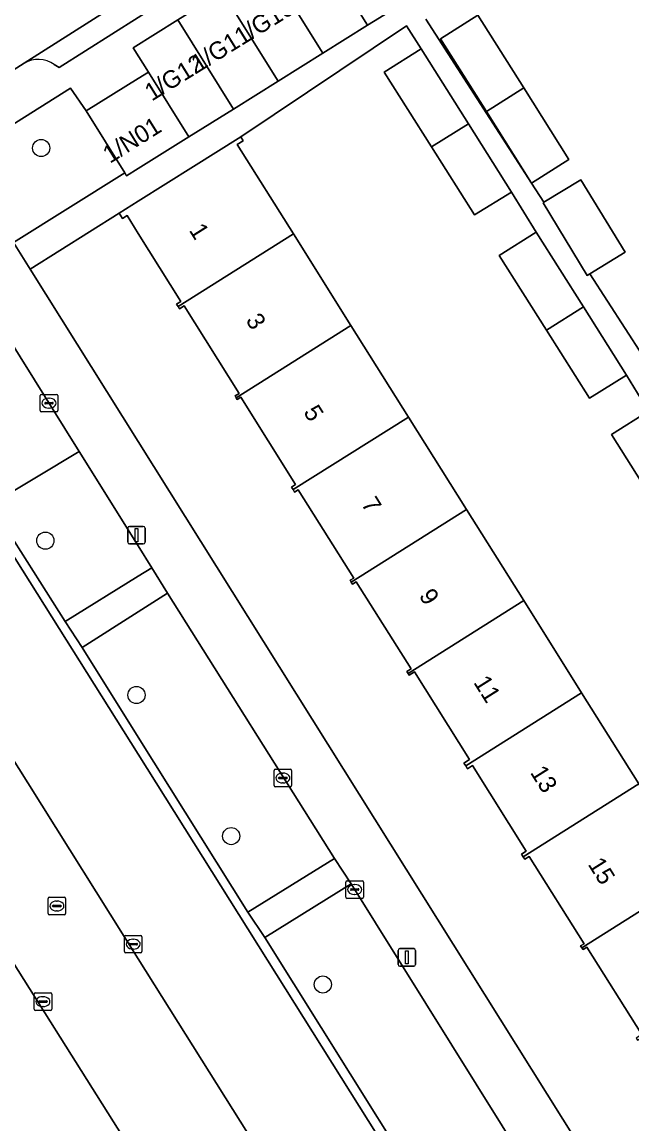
# Model space of a CAD drawing. Extents: x 160077 to 160948, y 386481 to 387498.
# Drawn here: x 160493.4 to 160528.1, y 386782.4 to 386845.2 of the extents above; entities that cross this region are included whole.
import ezdxf

# ---------------------------------------------------------------- set-up
doc = ezdxf.new("R2010")
doc.units = 0
for name, color, linetype in [('IMGEO_Boom', 7, 'Continuous'), ('IMGEO_Erf', 7, 'Continuous'), ('IMGEO_Groenvoorziening', 7, 'Continuous'), ('IMGEO_Kolk', 7, 'Continuous'), ('IMGEO_Lichtmast', 7, 'Continuous'), ('IMGEO_Pand', 7, 'Continuous'), ('IMGEO_Pand_nummerreeks', 7, 'Continuous'), ('IMGEO_Parkeervlak_open', 7, 'Continuous'), ('IMGEO_Rijbaan_lokaal_open', 7, 'Continuous'), ('IMGEO_Rioolput', 7, 'Continuous'), ('IMGEO_Voetpad_open', 7, 'Continuous')]:
    doc.layers.add(name, color=color, linetype=linetype)

msp = doc.modelspace()

# ---------------------------------------------------------------- linework, layer by layer
at = {"layer": 'IMGEO_Boom'}
for centre in [(160494.468, 386837.987), (160494.706, 386815.629), (160499.897, 386806.838), (160505.295, 386798.805), (160510.52, 386790.355)]:
    msp.add_circle(centre, 0.489, dxfattribs=at)
at = {"layer": 'IMGEO_Erf'}
msp.add_lwpolyline([(160522.416, 386835.99), (160519.84, 386840.073), (160517.231, 386844.212), (160519.359, 386845.554), (160521.969, 386841.416), (160524.544, 386837.332)], close=True, dxfattribs=at)
for points in [[(160529.827, 386817.16), (160526.976, 386821.668), (160529.07, 386822.996), (160527.823, 386825.053), (160525.713, 386823.751), (160523.266, 386827.62), (160520.575, 386831.875), (160522.669, 386833.203), (160521.27, 386835.483), (160519.16, 386834.181), (160516.713, 386838.05), (160514.022, 386842.305), (160516.116, 386843.633), (160515.286, 386844.946), (160505.836, 386838.631), (160505.98, 386838.401), (160505.645, 386838.19), (160508.843, 386833.1), (160512.119, 386827.886), (160515.396, 386822.67), (160518.708, 386817.399), (160521.966, 386812.214), (160525.268, 386806.959), (160528.526, 386801.773)], [(160516.381, 386845.329), (160522.416, 386835.99), (160523.119, 386834.899), (160525.219, 386836.185), (160527.742, 386832.055), (160525.741, 386830.829), (160530.763, 386823.035), (160546.111, 386822.428), (160546.21, 386824.94), (160553.278, 386824.66), (160553.179, 386822.148), (160554.431, 386822.098), (160554.53, 386824.611), (160559.386, 386824.418), (160564.241, 386824.226), (160564.142, 386821.714), (160566.735, 386821.612), (160566.834, 386824.124), (160571.69, 386823.932)], [(160528.702, 386787.499), (160525.566, 386792.477), (160525.351, 386792.338), (160525.279, 386792.445), (160525.207, 386792.552), (160525.406, 386792.677), (160522.284, 386797.646), (160522.03, 386797.487), (160521.94, 386797.63), (160521.849, 386797.775), (160522.115, 386797.942), (160519.049, 386802.821), (160518.762, 386802.64), (160518.66, 386802.802), (160518.558, 386802.965), (160518.876, 386803.165), (160515.741, 386808.154), (160515.439, 386807.964), (160515.374, 386808.067), (160515.308, 386808.172), (160515.545, 386808.321), (160512.422, 386813.292), (160512.211, 386813.16), (160512.142, 386813.268), (160512.075, 386813.375), (160512.279, 386813.502), (160509.122, 386818.527), (160508.907, 386818.392), (160508.819, 386818.533), (160508.73, 386818.675), (160508.967, 386818.824), (160505.84, 386823.802), (160505.632, 386823.671), (160505.576, 386823.77), (160505.519, 386823.871), (160505.748, 386824.014), (160502.614, 386829.002), (160502.347, 386828.834), (160502.266, 386828.963), (160502.185, 386829.092), (160502.435, 386829.249), (160500, 386833.124), (160499.363, 386834.138), (160499.106, 386833.977), (160498.914, 386834.282), (160493.843, 386831.09), (160500, 386821.271), (160533.22, 386768.294)]]:
    msp.add_lwpolyline(points, dxfattribs=at)
at = {"layer": 'IMGEO_Groenvoorziening'}
for points in [[(160491.599, 386834.684), (160492.889, 386832.611), (160499.231, 386836.575), (160497.03, 386840.097), (160496.129, 386841.406), (160492.636, 386839.201)], [(160484.287, 386836.124), (160481.322, 386834.24), (160491.654, 386817.735), (160496.638, 386820.704), (160487.431, 386835.412)], [(160492.95, 386815.59), (160495.843, 386811.033), (160500, 386813.607), (160500.779, 386814.089), (160500, 386815.333), (160496.638, 386820.704), (160491.654, 386817.735), (160490.344, 386816.955)]]:
    msp.add_lwpolyline(points, dxfattribs=at)
for points in [[(160506.249, 386794.478), (160511.177, 386797.531), (160501.675, 386812.637), (160500, 386811.578), (160496.797, 386809.553), (160500, 386804.445)], [(160520.143, 386772.386), (160525.003, 386775.498), (160512.129, 386796.086), (160507.211, 386793.022)]]:
    msp.add_lwpolyline(points, close=True, dxfattribs=at)
at = {"layer": 'IMGEO_Kolk'}
for p, q in [((160494.413, 386823.035), (160494.413, 386823.887)), ((160494.488, 386823.961), (160495.34, 386823.961)), ((160494.672, 386823.455), (160494.672, 386823.467)), ((160495.11, 386823.418), (160494.712, 386823.418)), ((160494.715, 386823.504), (160495.113, 386823.504)), ((160494.901, 386823.741), (160494.926, 386823.741)), ((160495.156, 386823.467), (160495.156, 386823.455)), ((160495.414, 386823.887), (160495.414, 386823.035)), ((160495.34, 386822.961), (160494.488, 386822.961)), ((160494.924, 386823.181), (160494.899, 386823.181)), ((160511.833, 386795.334), (160511.833, 386796.186)), ((160511.908, 386796.26), (160512.76, 386796.26)), ((160512.135, 386795.803), (160512.533, 386795.803)), ((160512.321, 386796.04), (160512.346, 386796.04)), ((160512.834, 386796.186), (160512.834, 386795.334)), ((160512.76, 386795.26), (160511.908, 386795.26)), ((160512.092, 386795.754), (160512.092, 386795.766)), ((160512.53, 386795.717), (160512.132, 386795.717)), ((160512.344, 386795.48), (160512.319, 386795.48)), ((160512.576, 386795.766), (160512.576, 386795.754)), ((160499.21, 386792.224), (160499.21, 386793.076)), ((160499.285, 386793.15), (160500.137, 386793.15)), ((160499.512, 386792.693), (160499.91, 386792.693)), ((160499.698, 386792.93), (160499.723, 386792.93)), ((160500.211, 386793.076), (160500.211, 386792.224)), ((160500.137, 386792.15), (160499.285, 386792.15)), ((160499.469, 386792.644), (160499.469, 386792.656)), ((160499.907, 386792.607), (160499.509, 386792.607)), ((160499.721, 386792.37), (160499.696, 386792.37)), ((160499.953, 386792.656), (160499.953, 386792.644)), ((160494.067, 386788.954), (160494.067, 386789.806)), ((160494.142, 386789.88), (160494.994, 386789.88)), ((160494.555, 386789.66), (160494.58, 386789.66)), ((160495.068, 386789.806), (160495.068, 386788.954)), ((160494.326, 386789.374), (160494.326, 386789.386)), ((160494.764, 386789.337), (160494.366, 386789.337)), ((160494.369, 386789.423), (160494.767, 386789.423)), ((160494.578, 386789.1), (160494.553, 386789.1)), ((160494.81, 386789.386), (160494.81, 386789.374)), ((160494.994, 386788.88), (160494.142, 386788.88))]:
    msp.add_line(p, q, dxfattribs=at)
for points in [[(160494.413, 386823.035), (160494.413, 386823.887)], [(160494.488, 386823.961), (160495.34, 386823.961)], [(160495.414, 386823.887), (160495.414, 386823.035)], [(160495.34, 386822.961), (160494.488, 386822.961)], [(160511.833, 386795.334), (160511.833, 386796.186)], [(160511.908, 386796.26), (160512.76, 386796.26)], [(160512.834, 386796.186), (160512.834, 386795.334)], [(160512.76, 386795.26), (160511.908, 386795.26)], [(160499.21, 386792.224), (160499.21, 386793.076)], [(160499.285, 386793.15), (160500.137, 386793.15)], [(160500.211, 386793.076), (160500.211, 386792.224)], [(160500.137, 386792.15), (160499.285, 386792.15)], [(160494.067, 386788.954), (160494.067, 386789.806)], [(160494.142, 386789.88), (160494.994, 386789.88)], [(160495.068, 386789.806), (160495.068, 386788.954)], [(160494.994, 386788.88), (160494.142, 386788.88)]]:
    msp.add_lwpolyline(points, dxfattribs=at)
for centre, radius, start, end in [((160494.49, 386823.885), 0.0765, 91.55205, 178.44795), ((160494.49, 386823.885), 0.0765, 91.55205, 178.44795), ((160494.712, 386823.464), 0.0403, 85.87752, 175.75265), ((160494.709, 386823.454), 0.0366, 178.93798, 274.71019), ((160495.113, 386823.461), 0.043, 264.86636, 352.45326), ((160495.117, 386823.466), 0.0386, 1.73085, 96.63898), ((160495.338, 386823.885), 0.0765, 1.55205, 88.44795), ((160495.338, 386823.885), 0.0765, 1.55205, 88.44795), ((160494.49, 386823.037), 0.0765, 181.55205, 268.44795), ((160494.49, 386823.037), 0.0765, 181.55205, 268.44795), ((160495.338, 386823.037), 0.0765, 271.55205, 358.44795), ((160495.338, 386823.037), 0.0765, 271.55205, 358.44795), ((160511.91, 386796.184), 0.0765, 91.55205, 178.44795), ((160511.91, 386796.184), 0.0765, 91.55205, 178.44795), ((160512.132, 386795.763), 0.0403, 85.87752, 175.75265), ((160512.537, 386795.765), 0.0386, 1.73085, 96.63898), ((160512.758, 386796.184), 0.0765, 1.55205, 88.44795), ((160512.758, 386796.184), 0.0765, 1.55205, 88.44795), ((160511.91, 386795.336), 0.0765, 181.55205, 268.44795), ((160511.91, 386795.336), 0.0765, 181.55205, 268.44795), ((160512.129, 386795.753), 0.0366, 178.93798, 274.71019), ((160512.533, 386795.76), 0.043, 264.86636, 352.45326), ((160512.758, 386795.336), 0.0765, 271.55205, 358.44795), ((160512.758, 386795.336), 0.0765, 271.55205, 358.44795), ((160499.287, 386793.074), 0.0765, 91.55205, 178.44795), ((160499.287, 386793.074), 0.0765, 91.55205, 178.44795), ((160499.509, 386792.653), 0.0403, 85.87752, 175.75265), ((160499.914, 386792.655), 0.0386, 1.73085, 96.63898), ((160500.135, 386793.074), 0.0765, 1.55205, 88.44795), ((160500.135, 386793.074), 0.0765, 1.55205, 88.44795), ((160499.287, 386792.226), 0.0765, 181.55205, 268.44795), ((160499.287, 386792.226), 0.0765, 181.55205, 268.44795), ((160499.506, 386792.643), 0.0366, 178.93798, 274.71019), ((160499.91, 386792.65), 0.043, 264.86636, 352.45326), ((160500.135, 386792.226), 0.0765, 271.55205, 358.44795), ((160500.135, 386792.226), 0.0765, 271.55205, 358.44795), ((160494.144, 386789.804), 0.0765, 91.55205, 178.44795), ((160494.144, 386789.804), 0.0765, 91.55205, 178.44795), ((160494.992, 386789.804), 0.0765, 1.55205, 88.44795), ((160494.992, 386789.804), 0.0765, 1.55205, 88.44795), ((160494.144, 386788.956), 0.0765, 181.55205, 268.44795), ((160494.144, 386788.956), 0.0765, 181.55205, 268.44795), ((160494.366, 386789.383), 0.0403, 85.87752, 175.75265), ((160494.363, 386789.373), 0.0366, 178.93798, 274.71019), ((160494.767, 386789.38), 0.043, 264.86636, 352.45326), ((160494.771, 386789.385), 0.0386, 1.73085, 96.63898), ((160494.992, 386788.956), 0.0765, 271.55205, 358.44795), ((160494.992, 386788.956), 0.0765, 271.55205, 358.44795)]:
    msp.add_arc(centre, radius, start, end, dxfattribs=at)
for centre, major_axis, ratio, start_param, end_param in [((160494.9, 386823.461), (-0.387, 0.002), 0.722429, 4.712389, 7.853982), ((160494.925, 386823.461), (-0.39, 0.002), 0.717154, 1.570796, 4.712389), ((160512.32, 386795.76), (-0.387, 0.002), 0.722429, 4.712389, 7.853982), ((160512.345, 386795.76), (-0.39, 0.002), 0.717154, 1.570796, 4.712389), ((160499.697, 386792.65), (-0.387, 0.002), 0.722429, 4.712389, 7.853982), ((160499.722, 386792.65), (-0.39, 0.002), 0.717154, 1.570796, 4.712389), ((160494.554, 386789.38), (-0.387, 0.002), 0.722429, 4.712389, 7.853982), ((160494.579, 386789.38), (-0.39, 0.002), 0.717154, 1.570796, 4.712389)]:
    msp.add_ellipse(centre, major_axis=major_axis, ratio=ratio, start_param=start_param, end_param=end_param, dxfattribs=at)
at = {"layer": 'IMGEO_Lichtmast'}
for p, q in [((160499.398, 386815.542), (160499.398, 386816.342)), ((160499.398, 386816.342), (160499.398, 386815.542)), ((160499.498, 386816.442), (160500.288, 386816.442)), ((160500.288, 386816.442), (160499.498, 386816.442)), ((160500.388, 386816.342), (160500.388, 386815.542)), ((160500.388, 386815.542), (160500.388, 386816.342)), ((160500.288, 386815.442), (160499.498, 386815.442)), ((160499.498, 386815.442), (160500.288, 386815.442)), ((160514.806, 386791.496), (160514.806, 386792.296)), ((160514.806, 386792.296), (160514.806, 386791.496)), ((160514.906, 386792.396), (160515.696, 386792.396)), ((160515.696, 386792.396), (160514.906, 386792.396)), ((160515.796, 386792.296), (160515.796, 386791.496)), ((160515.796, 386791.496), (160515.796, 386792.296)), ((160515.696, 386791.396), (160514.906, 386791.396)), ((160514.906, 386791.396), (160515.696, 386791.396))]:
    msp.add_line(p, q, dxfattribs=at)
for points in [[(160499.818, 386816.317), (160499.968, 386816.317), (160499.968, 386815.567), (160499.818, 386815.567), (160499.818, 386816.317)], [(160515.226, 386792.271), (160515.376, 386792.271), (160515.376, 386791.521), (160515.226, 386791.521), (160515.226, 386792.271)]]:
    msp.add_lwpolyline(points, dxfattribs=at)
for centre, start, end in [((160499.498, 386816.342), 90, 180), ((160499.498, 386816.342), 90, 180), ((160500.288, 386816.342), 0, 90), ((160500.288, 386816.342), 360, 90), ((160499.498, 386815.542), 180, 270), ((160499.498, 386815.542), 180, 270), ((160500.288, 386815.542), 270, 0), ((160500.288, 386815.542), 270, 0), ((160514.906, 386792.296), 90, 180), ((160514.906, 386792.296), 90, 180), ((160515.696, 386792.296), 0, 90), ((160515.696, 386792.296), 360, 90), ((160514.906, 386791.496), 180, 270), ((160514.906, 386791.496), 180, 270), ((160515.696, 386791.496), 270, 0), ((160515.696, 386791.496), 270, 0)]:
    msp.add_arc(centre, 0.1, start, end, dxfattribs=at)
at = {"layer": 'IMGEO_Pand'}
for points in [[(160512.43, 386851.65), (160509.886, 386850.06), (160513.061, 386844.979), (160515.606, 386846.569)], [(160510.516, 386843.389), (160513.061, 386844.979), (160509.886, 386850.06), (160507.341, 386848.47)], [(160507.341, 386848.47), (160504.796, 386846.88), (160507.972, 386841.799), (160510.516, 386843.389)], [(160505.427, 386840.208), (160507.972, 386841.799), (160504.796, 386846.88), (160502.252, 386845.29)], [(160519.84, 386840.073), (160521.969, 386841.416), (160519.359, 386845.554), (160517.231, 386844.212)], [(160502.882, 386838.618), (160505.427, 386840.208), (160502.252, 386845.29), (160499.707, 386843.7), (160500.574, 386842.312)], [(160516.116, 386843.633), (160514.022, 386842.305), (160516.713, 386838.05), (160518.812, 386839.37)], [(160500.574, 386842.312), (160500, 386841.953), (160497.03, 386840.097), (160499.231, 386836.575), (160499.338, 386836.404), (160500, 386836.818), (160502.882, 386838.618)], [(160521.969, 386841.416), (160519.84, 386840.073), (160522.416, 386835.99), (160524.544, 386837.332)], [(160519.16, 386834.181), (160521.27, 386835.483), (160518.812, 386839.37), (160516.713, 386838.05)], [(160508.843, 386833.1), (160505.645, 386838.19), (160505.98, 386838.401), (160505.836, 386838.631), (160503.148, 386836.942), (160500, 386834.964), (160498.914, 386834.282), (160499.106, 386833.977), (160499.363, 386834.138), (160500, 386833.124), (160502.435, 386829.249), (160502.185, 386829.092), (160502.266, 386828.963)], [(160523.119, 386834.899), (160523.067, 386834.867), (160525.59, 386830.737), (160525.741, 386830.829), (160527.742, 386832.055), (160525.219, 386836.185)], [(160502.266, 386828.963), (160502.347, 386828.834), (160502.614, 386829.002), (160505.748, 386824.014), (160505.519, 386823.871), (160505.576, 386823.77), (160512.119, 386827.886), (160508.843, 386833.1)], [(160522.669, 386833.203), (160520.575, 386831.875), (160523.266, 386827.62), (160525.365, 386828.94)], [(160525.713, 386823.751), (160527.823, 386825.053), (160525.365, 386828.94), (160523.266, 386827.62)], [(160515.396, 386822.67), (160512.119, 386827.886), (160505.576, 386823.77), (160505.632, 386823.671), (160505.84, 386823.802), (160508.967, 386818.824), (160508.73, 386818.675), (160508.819, 386818.533)], [(160531.926, 386818.48), (160529.07, 386822.996), (160526.976, 386821.668), (160529.827, 386817.16)], [(160508.819, 386818.533), (160508.907, 386818.392), (160509.122, 386818.527), (160512.279, 386813.502), (160512.075, 386813.375), (160512.142, 386813.268), (160518.708, 386817.399), (160515.396, 386822.67)], [(160521.966, 386812.214), (160518.708, 386817.399), (160512.142, 386813.268), (160512.211, 386813.16), (160512.422, 386813.292), (160515.545, 386808.321), (160515.308, 386808.172), (160515.374, 386808.067)], [(160515.374, 386808.067), (160515.439, 386807.964), (160515.741, 386808.154), (160518.876, 386803.165), (160518.558, 386802.965), (160518.66, 386802.802), (160525.268, 386806.959), (160521.966, 386812.214)], [(160528.526, 386801.773), (160525.268, 386806.959), (160518.66, 386802.802), (160518.762, 386802.64), (160519.049, 386802.821), (160522.115, 386797.942), (160521.849, 386797.775), (160521.94, 386797.63)], [(160531.807, 386796.552), (160528.526, 386801.773), (160521.94, 386797.63), (160522.03, 386797.487), (160522.284, 386797.646), (160525.406, 386792.677), (160525.207, 386792.552), (160525.279, 386792.445)], [(160535.077, 386791.347), (160537.583, 386792.921), (160534.313, 386798.126), (160531.807, 386796.552), (160525.279, 386792.445), (160525.351, 386792.338), (160525.566, 386792.477), (160528.702, 386787.499), (160528.377, 386787.294), (160528.45, 386787.178)]]:
    msp.add_lwpolyline(points, close=True, dxfattribs=at)
at = {"layer": 'IMGEO_Parkeervlak_open'}
for points in [[(160506.313, 386770.262), (160484.216, 386805.302), (160473.247, 386822.633)], [(160525.691, 386762.559), (160500, 386803.462), (160492.571, 386815.272)], [(160485.3, 386815.198), (160493.709, 386801.834), (160500, 386791.819), (160509.431, 386776.805), (160521.564, 386757.591), (160525.066, 386759.804)]]:
    msp.add_lwpolyline(points, dxfattribs=at)
at = {"layer": 'IMGEO_Rijbaan_lokaal_open'}
for points in [[(160480.194, 386834.45), (160485.71, 386837.9), (160486.605, 386838.46), (160493.492, 386842.826), (160500, 386846.953), (160519.43, 386859.272), (160532.054, 386867.023), (160535.096, 386868.978), (160531.426, 386874.903), (160528.456, 386873.047), (160507.768, 386860.017), (160500, 386855.149), (160485.425, 386846.014), (160475.724, 386839.906)], [(160500, 386791.819), (160493.709, 386801.834), (160485.3, 386815.198), (160478.374, 386826.207)], [(160473.247, 386822.633), (160484.216, 386805.302), (160506.313, 386770.262), (160512.49, 386760.505), (160513.375, 386759.047), (160516.389, 386754.32), (160516.594, 386754.45), (160521.564, 386757.591), (160509.431, 386776.805), (160500, 386791.819)]]:
    msp.add_lwpolyline(points, dxfattribs=at)
at = {"layer": 'IMGEO_Rioolput'}
for p, q in [((160507.74, 386801.685), (160507.74, 386802.537)), ((160507.815, 386802.611), (160508.667, 386802.611)), ((160507.999, 386802.105), (160507.999, 386802.117)), ((160508.042, 386802.154), (160508.44, 386802.154)), ((160508.228, 386802.391), (160508.253, 386802.391)), ((160508.483, 386802.117), (160508.483, 386802.105)), ((160508.741, 386802.537), (160508.741, 386801.685)), ((160508.667, 386801.611), (160507.815, 386801.611)), ((160508.437, 386802.068), (160508.039, 386802.068)), ((160508.251, 386801.831), (160508.226, 386801.831)), ((160494.861, 386794.395), (160494.861, 386795.247)), ((160494.936, 386795.321), (160495.788, 386795.321)), ((160495.862, 386795.247), (160495.862, 386794.395)), ((160495.12, 386794.815), (160495.12, 386794.827)), ((160495.558, 386794.778), (160495.16, 386794.778)), ((160495.163, 386794.864), (160495.561, 386794.864)), ((160495.349, 386795.101), (160495.374, 386795.101)), ((160495.604, 386794.827), (160495.604, 386794.815)), ((160495.788, 386794.321), (160494.936, 386794.321)), ((160495.372, 386794.541), (160495.347, 386794.541))]:
    msp.add_line(p, q, dxfattribs=at)
for points in [[(160507.74, 386801.685), (160507.74, 386802.537)], [(160507.815, 386802.611), (160508.667, 386802.611)], [(160508.741, 386802.537), (160508.741, 386801.685)], [(160508.667, 386801.611), (160507.815, 386801.611)], [(160494.861, 386794.395), (160494.861, 386795.247)], [(160494.936, 386795.321), (160495.788, 386795.321)], [(160495.862, 386795.247), (160495.862, 386794.395)], [(160495.788, 386794.321), (160494.936, 386794.321)]]:
    msp.add_lwpolyline(points, dxfattribs=at)
for centre, radius, start, end in [((160507.817, 386802.535), 0.0765, 91.55205, 178.44795), ((160507.817, 386802.535), 0.0765, 91.55205, 178.44795), ((160508.039, 386802.114), 0.0403, 85.87752, 175.75265), ((160508.036, 386802.104), 0.0366, 178.93798, 274.71019), ((160508.44, 386802.111), 0.043, 264.86636, 352.45326), ((160508.444, 386802.116), 0.0386, 1.73085, 96.63898), ((160508.665, 386802.535), 0.0765, 1.55205, 88.44795), ((160508.665, 386802.535), 0.0765, 1.55205, 88.44795), ((160507.817, 386801.687), 0.0765, 181.55205, 268.44795), ((160507.817, 386801.687), 0.0765, 181.55205, 268.44795), ((160508.665, 386801.687), 0.0765, 271.55205, 358.44795), ((160508.665, 386801.687), 0.0765, 271.55205, 358.44795), ((160494.938, 386795.245), 0.0765, 91.55205, 178.44795), ((160494.938, 386795.245), 0.0765, 91.55205, 178.44795), ((160495.786, 386795.245), 0.0765, 1.55205, 88.44795), ((160495.786, 386795.245), 0.0765, 1.55205, 88.44795), ((160495.16, 386794.824), 0.0403, 85.87752, 175.75265), ((160495.157, 386794.814), 0.0366, 178.93798, 274.71019), ((160495.561, 386794.821), 0.043, 264.86636, 352.45326), ((160495.565, 386794.826), 0.0386, 1.73085, 96.63898), ((160494.938, 386794.397), 0.0765, 181.55205, 268.44795), ((160494.938, 386794.397), 0.0765, 181.55205, 268.44795), ((160495.786, 386794.397), 0.0765, 271.55205, 358.44795), ((160495.786, 386794.397), 0.0765, 271.55205, 358.44795)]:
    msp.add_arc(centre, radius, start, end, dxfattribs=at)
for centre, major_axis, ratio, start_param, end_param in [((160508.227, 386802.111), (-0.387, 0.002), 0.722429, 4.712389, 7.853982), ((160508.252, 386802.111), (-0.39, 0.002), 0.717154, 1.570796, 4.712389), ((160495.348, 386794.821), (-0.387, 0.002), 0.722429, 4.712389, 7.853982), ((160495.373, 386794.821), (-0.39, 0.002), 0.717154, 1.570796, 4.712389)]:
    msp.add_ellipse(centre, major_axis=major_axis, ratio=ratio, start_param=start_param, end_param=end_param, dxfattribs=at)
at = {"layer": 'IMGEO_Voetpad_open'}
for points in [[(160532.054, 386867.023), (160519.43, 386859.272), (160500, 386846.953), (160493.492, 386842.826)], [(160496.129, 386841.406), (160497.03, 386840.097), (160500, 386841.953), (160500.574, 386842.312), (160499.707, 386843.7), (160502.252, 386845.29), (160504.796, 386846.88), (160507.341, 386848.47), (160509.886, 386850.06), (160512.43, 386851.65), (160514.975, 386853.24), (160517.52, 386854.831), (160520.064, 386856.421), (160522.609, 386858.011), (160525.154, 386859.601), (160527.698, 386861.191), (160530.243, 386862.781), (160532.309, 386864.071), (160531.77, 386865.357), (160520.113, 386858.179), (160500, 386845.428), (160495.486, 386842.566), (160495.209, 386842.751)], [(160495.209, 386842.751), (160495.486, 386842.566), (160500, 386845.428), (160520.113, 386858.179)], [(160515.606, 386846.569), (160513.061, 386844.979), (160510.516, 386843.389), (160507.972, 386841.799), (160505.427, 386840.208), (160502.882, 386838.618), (160500, 386836.818), (160499.338, 386836.404), (160499.231, 386836.575), (160492.889, 386832.611), (160493.843, 386831.09), (160498.914, 386834.282), (160500, 386834.964), (160503.148, 386836.942), (160505.836, 386838.631), (160515.286, 386844.946), (160516.116, 386843.633), (160518.812, 386839.37), (160521.27, 386835.483), (160522.669, 386833.203), (160525.365, 386828.94), (160527.823, 386825.053), (160529.07, 386822.996)], [(160571.591, 386821.419), (160566.735, 386821.612), (160564.142, 386821.714), (160559.287, 386821.906), (160554.431, 386822.098), (160553.179, 386822.148), (160546.111, 386822.428), (160530.763, 386823.035), (160525.741, 386830.829), (160525.59, 386830.737), (160523.067, 386834.867), (160523.119, 386834.899), (160522.416, 386835.99), (160516.381, 386845.329)], [(160493.492, 386842.826), (160486.605, 386838.46), (160485.71, 386837.9), (160487.101, 386835.824), (160492.636, 386839.201), (160496.129, 386841.406)], [(160487.431, 386835.412), (160496.638, 386820.704), (160500, 386815.333), (160500.779, 386814.089), (160501.675, 386812.637), (160511.177, 386797.531), (160512.129, 386796.086), (160525.003, 386775.498), (160525.866, 386774.021), (160529.409, 386768.538), (160530.848, 386766.312)], [(160533.22, 386768.294), (160500, 386821.271), (160493.843, 386831.09), (160492.889, 386832.611), (160491.599, 386834.684)], [(160492.571, 386815.272), (160500, 386803.462), (160525.691, 386762.559)], [(160500, 386804.445), (160496.797, 386809.553), (160495.843, 386811.033), (160492.95, 386815.59)], [(160525.066, 386759.804), (160527.273, 386761.043), (160524.568, 386765.372), (160521.015, 386771.06), (160520.143, 386772.386), (160507.211, 386793.022), (160506.249, 386794.478), (160500, 386804.445)]]:
    msp.add_lwpolyline(points, dxfattribs=at)
for points in [[(160501.675, 386812.637), (160500.779, 386814.089), (160500, 386813.607), (160495.843, 386811.033), (160496.797, 386809.553), (160500, 386811.578)], [(160512.129, 386796.086), (160511.177, 386797.531), (160506.249, 386794.478), (160507.211, 386793.022)]]:
    msp.add_lwpolyline(points, close=True, dxfattribs=at)
msp.add_arc((160494.289, 386841.374), 1.657, 56.25078, 118.74694, dxfattribs=at)
msp.add_arc((160494.289, 386841.374), 1.657, 56.25078, 118.74694, dxfattribs=at)

# ---------------------------------------------------------------- texts
at = {"layer": 'IMGEO_Pand_nummerreeks'}
for s, rotation, p in [('1/G10', 31.7675, (160505.88, 386843.793)), ('1/G11', 31.7675, (160503.419, 386842.27)), ('1/G12', 31.7675, (160500.769, 386840.629)), ('1/N01', 31.94279, (160498.385, 386837.084)), ('1', 302.19193, (160502.864, 386833.308)), ('3', 302.19193, (160506.094, 386828.177)), ('5', 302.19193, (160509.385, 386822.949)), ('7', 302.19193, (160512.676, 386817.721)), ('9', 302.19193, (160515.967, 386812.494)), ('11', 302.19193, (160519.074, 386807.559)), ('13', 302.19193, (160522.305, 386802.427)), ('15', 302.19193, (160525.596, 386797.199))]:
    msp.add_text(s, height=1, rotation=rotation, dxfattribs=at).set_placement(p)

doc.saveas('drawing.dxf')
